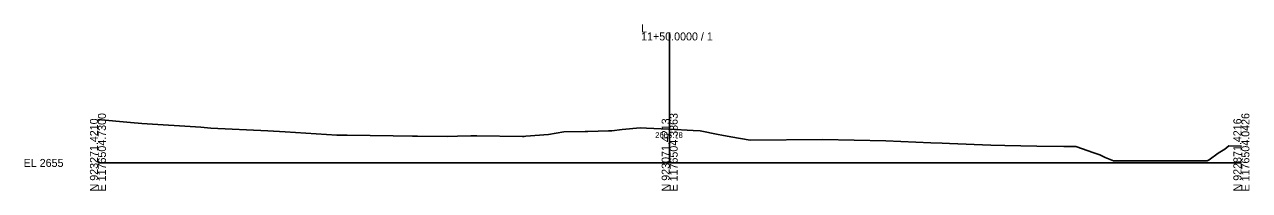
# Model space of a CAD drawing. Extents: x -26 to 1403, y -10 to 9563.
# Drawn here: x -25.7 to 402.8, y 1490.3 to 1548.6 of the extents above; entities that cross this region are included whole.
import ezdxf

# ---------------------------------------------------------------- set-up
doc = ezdxf.new("R2010")
doc.units = 0
for name, color, linetype in [('Exist Cross Section Cell', 7, 'Continuous'), ('Exist XS Center Line Elevation Label', 7, 'Continuous'), ('Exist XS Ground Line', 7, 'Continuous')]:
    doc.layers.add(name, color=color, linetype=linetype)

msp = doc.modelspace()

# ---------------------------------------------------------------- linework, layer by layer
at = {"layer": 'Exist Cross Section Cell'}
for p, q in [((200, 1500), (200, 1545.76)), ((0, 1500), (200, 1500)), ((200, 1500), (400, 1500))]:
    msp.add_line(p, q, dxfattribs=at)
at = {"layer": 'Exist XS Ground Line'}
for p, q in [((0, 1515.25), (11.38, 1514.16)), ((11.38, 1514.16), (15.37, 1513.86)), ((15.37, 1513.86), (36.04, 1512.49)), ((36.04, 1512.49), (39.48, 1512.23)), ((39.48, 1512.23), (59.41, 1511.27)), ((59.41, 1511.27), (65.54, 1510.9)), ((65.54, 1510.9), (83.59, 1509.77)), ((83.59, 1509.77), (87.21, 1509.73)), ((87.21, 1509.73), (103.27, 1509.49)), ((103.27, 1509.49), (109.99, 1509.43)), ((109.99, 1509.43), (111.84, 1509.4)), ((111.84, 1509.4), (122.13, 1509.27)), ((122.13, 1509.27), (125.77, 1509.36)), ((125.77, 1509.36), (130.49, 1509.5)), ((130.49, 1509.5), (132.57, 1509.46)), ((132.57, 1509.46), (148.51, 1509.32)), ((148.51, 1509.32), (149.05, 1509.32)), ((149.05, 1509.32), (149.73, 1509.36)), ((149.73, 1509.36), (157.56, 1509.99)), ((157.56, 1509.99), (162.96, 1510.94)), ((162.96, 1510.94), (170.49, 1511.06)), ((170.49, 1511.06), (171.43, 1511.07)), ((171.43, 1511.07), (178.64, 1511.2)), ((178.64, 1511.2), (179.77, 1511.26)), ((179.77, 1511.26), (183.39, 1511.67)), ((183.39, 1511.67), (189.65, 1512.32)), ((189.65, 1512.32), (191.91, 1512.21)), ((191.91, 1512.21), (199.58, 1511.8)), ((199.58, 1511.8), (200, 1511.78)), ((200, 1511.78), (208.2, 1511.35)), ((208.2, 1511.35), (210.65, 1511.22)), ((210.65, 1511.22), (216.92, 1509.98)), ((216.92, 1509.98), (218.21, 1509.74)), ((218.21, 1509.74), (221.38, 1509.12)), ((221.38, 1509.12), (228.11, 1507.98)), ((228.11, 1507.98), (253.52, 1508.23)), ((253.52, 1508.23), (275.66, 1507.73)), ((275.66, 1507.73), (291.31, 1507.07)), ((291.31, 1507.07), (295.27, 1506.88)), ((295.27, 1506.88), (297.89, 1506.8)), ((297.89, 1506.8), (312.37, 1506.22)), ((312.37, 1506.22), (317.22, 1506.11)), ((317.22, 1506.11), (328.4, 1505.9)), ((328.4, 1505.9), (337.92, 1505.8)), ((337.92, 1505.8), (342.04, 1505.8)), ((342.04, 1505.8), (348.43, 1503.54)), ((391.92, 1503.39), (394.17, 1504.84)), ((394.17, 1504.84), (395.64, 1505.97)), ((395.64, 1505.97), (400, 1505.92)), ((348.43, 1503.54), (350.47, 1502.81)), ((350.47, 1502.81), (352.34, 1501.93)), ((352.34, 1501.93), (355.22, 1500.73)), ((355.22, 1500.73), (369.67, 1500.73)), ((369.67, 1500.73), (388.08, 1500.73)), ((388.08, 1500.73), (388.76, 1501.14)), ((388.76, 1501.14), (391.92, 1503.39))]:
    msp.add_line(p, q, dxfattribs=at)

# ---------------------------------------------------------------- texts
at = {"layer": 'Exist Cross Section Cell'}
for s, p in [('L', (190, 1545.76)), ('11+50.0000 / 1', (190, 1542.96)), ('EL 2655', (-26, 1498.6))]:
    msp.add_text(s, height=2.8, dxfattribs=at).set_placement(p)
for s, p in [('E 1176504.7300', (2.8, 1490)), ('E 1176504.3863', (202.8, 1490)), ('E 1176504.0426', (402.8, 1490)), ('N 923271.4210', (0, 1490)), ('N 923071.4213', (200, 1490)), ('N 922871.4216', (400, 1490))]:
    msp.add_text(s, height=2.8, rotation=90, dxfattribs=at).set_placement(p)
at = {"layer": 'Exist XS Center Line Elevation Label'}
msp.add_text('2666.78', height=2, dxfattribs=at).set_placement((194.93, 1508.78))

doc.saveas('drawing.dxf')
